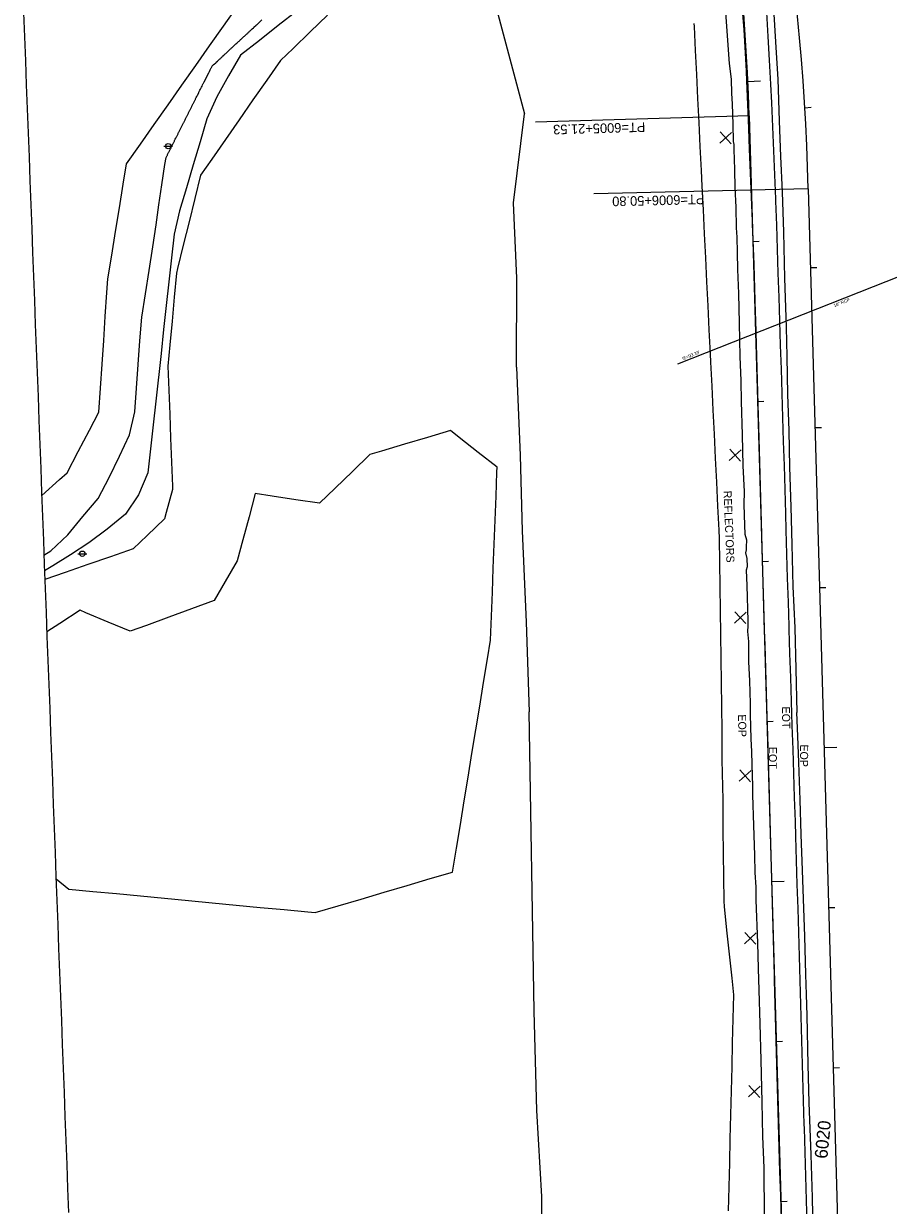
# Model space of a CAD drawing. Extents: x 2132221 to 2141942, y 535736 to 547298.
# Drawn here: x 2136695 to 2137235, y 540505 to 541244 of the extents above; entities that cross this region are included whole.
import ezdxf

# ---------------------------------------------------------------- set-up
doc = ezdxf.new("R2010")
doc.units = 0
for name, color, linetype in [('RD_EX_DR_Inlet_txCode', 7, 'Continuous'), ('RD_EX_DR_Pipe', 7, 'Continuous'), ('RD_EX_DR_Pipe_txCode', 7, 'Continuous'), ('RD_EX_Driveway', 7, 'Continuous'), ('RD_EX_Fence_Other', 7, 'Continuous'), ('RD_EX_Misc', 7, 'Continuous'), ('RD_EX_Misc_txCode', 7, 'Continuous'), ('RD_EX_Road', 7, 'Continuous'), ('RD_EX_Road_txCode', 7, 'Continuous'), ('RD_EX_SU_Pole', 7, 'Continuous'), ('RD_EX_VEG', 7, 'Continuous'), ('RD_HC_Cl', 7, 'Continuous'), ('RD_HC_Data', 7, 'Continuous'), ('RD_HC_Data_Tic', 7, 'Continuous'), ('RD_HC_TX_Sta50', 7, 'Continuous'), ('TOPO_E_TLIML-Line', 7, 'Continuous')]:
    doc.layers.add(name, color=color, linetype=linetype)

msp = doc.modelspace()

# ---------------------------------------------------------------- linework, layer by layer
at = {"layer": 'RD_EX_DR_Pipe'}
msp.add_line((2137103.49, 541031.08), (2137305.29, 541110.96), dxfattribs=at)
at = {"layer": 'RD_EX_Driveway'}
for points in [[(2136865.7, 541251.69), (2136853.89, 541242.43), (2136842.09, 541233.18), (2136830.29, 541223.93), (2136822.83, 541210.96), (2136815.56, 541197.84), (2136809.39, 541184.26), (2136805.09, 541169.89), (2136800.8, 541155.52), (2136796.51, 541141.15), (2136792.22, 541126.77), (2136788.94, 541112.2), (2136787.29, 541097.29), (2136785.64, 541082.38), (2136783.99, 541067.47), (2136782.33, 541052.56), (2136780.68, 541037.66), (2136777.38, 541007.84), (2136775.73, 540992.93), (2136774.08, 540978.02), (2136772.42, 540963.12), (2136766.71, 540949.33), (2136758.43, 540937.19), (2136747.1, 540927.78), (2136735.53, 540919.33), (2136724.2, 540911.75), (2136713.05, 540904.91), (2136707.93, 540901.76)], [(2136707.56, 540911.64), (2136711.88, 540914.22), (2136722.45, 540924.38), (2136731.94, 540935.72), (2136741.43, 540947.07), (2136748.29, 540960.11), (2136754.65, 540973.48), (2136761.01, 540986.85), (2136764.25, 541001.06), (2136765.31, 541015.85), (2136766.38, 541030.64), (2136767.44, 541045.44), (2136768.7, 541060.21), (2136773.23, 541089.52), (2136775.49, 541104.18), (2136777.57, 541117.87), (2136779.42, 541130.44), (2136781.27, 541143), (2136783.13, 541155.56), (2136783.88, 541160.06), (2136784.26, 541160.82), (2136784.45, 541161.2), (2136784.64, 541161.58), (2136784.83, 541161.95), (2136785.02, 541162.33), (2136785.21, 541162.71), (2136785.4, 541163.09), (2136785.59, 541163.46), (2136785.78, 541163.84), (2136785.97, 541164.22), (2136786.16, 541164.6), (2136786.35, 541164.98), (2136786.54, 541165.35), (2136786.73, 541165.73), (2136786.92, 541166.11), (2136787.11, 541166.49), (2136787.3, 541166.86), (2136787.49, 541167.24), (2136787.68, 541167.62), (2136788.63, 541169.51), (2136788.82, 541169.89), (2136789.01, 541170.27), (2136789.2, 541170.64), (2136789.39, 541171.02), (2136789.58, 541171.4), (2136789.96, 541172.15), (2136790.15, 541172.53), (2136790.34, 541172.91), (2136790.53, 541173.29), (2136790.72, 541173.67), (2136790.91, 541174.04), (2136791.1, 541174.42), (2136791.29, 541174.8), (2136791.48, 541175.18), (2136791.67, 541175.55), (2136791.86, 541175.93), (2136792.05, 541176.31), (2136792.24, 541176.69), (2136792.43, 541177.07), (2136792.62, 541177.44), (2136794.71, 541181.6), (2136794.9, 541181.98), (2136795.09, 541182.36), (2136795.28, 541182.73), (2136795.47, 541183.11), (2136795.66, 541183.49), (2136796.04, 541184.24), (2136796.23, 541184.62), (2136796.42, 541185), (2136796.61, 541185.38), (2136796.8, 541185.76), (2136796.99, 541186.13), (2136797.18, 541186.51), (2136797.37, 541186.89), (2136797.56, 541187.27), (2136797.75, 541187.65), (2136797.94, 541188.02), (2136798.13, 541188.4), (2136798.32, 541188.78), (2136798.51, 541189.16), (2136798.7, 541189.53), (2136798.89, 541189.91), (2136799.08, 541190.29), (2136799.46, 541191.05), (2136799.65, 541191.42), (2136799.84, 541191.8), (2136800.03, 541192.18), (2136800.22, 541192.56), (2136800.41, 541192.93), (2136800.6, 541193.31), (2136800.79, 541193.69), (2136800.98, 541194.07), (2136801.17, 541194.45), (2136801.36, 541194.82), (2136801.55, 541195.2), (2136801.74, 541195.58), (2136801.93, 541195.96), (2136802.12, 541196.34), (2136802.31, 541196.71), (2136802.69, 541197.47), (2136803.07, 541198.22), (2136803.45, 541198.98), (2136804.21, 541200.49), (2136804.4, 541200.87), (2136804.59, 541201.25), (2136804.78, 541201.62), (2136804.97, 541202), (2136805.35, 541202.76), (2136805.54, 541203.14), (2136805.73, 541203.51), (2136805.92, 541203.89), (2136806.3, 541204.65), (2136806.68, 541205.4), (2136806.87, 541205.78), (2136807.06, 541206.16), (2136807.25, 541206.54), (2136807.63, 541207.29), (2136810.48, 541212.96), (2136810.67, 541213.34), (2136810.86, 541213.72), (2136811.43, 541214.85), (2136811.62, 541215.23), (2136812, 541215.98), (2136812.19, 541216.36), (2136812.57, 541217.12), (2136812.89, 541217.43), (2136813.22, 541217.73), (2136813.55, 541218.04), (2136813.88, 541218.35), (2136814.88, 541219.27), (2136815.21, 541219.58), (2136815.87, 541220.19), (2136816.2, 541220.5), (2136816.53, 541220.8), (2136816.86, 541221.11), (2136817.19, 541221.42), (2136817.52, 541221.72), (2136817.85, 541222.03), (2136818.18, 541222.34), (2136818.84, 541222.95), (2136819.17, 541223.26), (2136819.84, 541223.87), (2136820.17, 541224.18), (2136820.83, 541224.79), (2136821.16, 541225.1), (2136821.49, 541225.41), (2136821.82, 541225.72), (2136822.15, 541226.02), (2136824.14, 541227.87), (2136824.47, 541228.17), (2136824.8, 541228.48), (2136825.13, 541228.79), (2136826.12, 541229.71), (2136826.45, 541230.01), (2136826.78, 541230.32), (2136827.44, 541230.94), (2136828.1, 541231.55), (2136828.43, 541231.86), (2136829.1, 541232.47), (2136829.43, 541232.78), (2136830.09, 541233.39), (2136830.42, 541233.7), (2136830.75, 541234.01), (2136831.08, 541234.31), (2136831.41, 541234.62), (2136831.74, 541234.93), (2136832.4, 541235.54), (2136832.73, 541235.85), (2136834.06, 541237.08), (2136834.39, 541237.38), (2136834.72, 541237.69), (2136835.05, 541238), (2136835.38, 541238.3), (2136835.71, 541238.61), (2136836.04, 541238.92), (2136836.37, 541239.23), (2136836.7, 541239.53), (2136837.69, 541240.45), (2136838.36, 541241.07), (2136838.69, 541241.38), (2136840.01, 541242.6), (2136840.34, 541242.91), (2136840.67, 541243.22), (2136843.65, 541245.98)]]:
    msp.add_lwpolyline(points, dxfattribs=at)
at = {"layer": 'RD_EX_Fence_Other'}
for p, q in [((2136990.99, 541249.71), (2137007.68, 541187.23)), ((2137013.82, 540626.7), (2137010.55, 540813.69))]:
    msp.add_line(p, q, dxfattribs=at)
for points in [[(2137002.61, 541029.05), (2137002.81, 541084.7), (2137000.84, 541131.72), (2137007.68, 541187.23)], [(2137002.61, 541029.05), (2137004.93, 540973.95), (2137006.19, 540926.7), (2137008.67, 540869.81), (2137010.55, 540813.69)], [(2137019.03, 540453.67), (2137018.59, 540510.97), (2137015.47, 540564.68), (2137013.82, 540626.7)]]:
    msp.add_lwpolyline(points, dxfattribs=at)
at = {"layer": 'RD_EX_Misc'}
for p, q in [((2137129.72, 541168.95), (2137137.07, 541175.74)), ((2137130, 541176.02), (2137136.78, 541168.67)), ((2137135.62, 540970.7), (2137142.96, 540977.48)), ((2137135.9, 540977.77), (2137142.68, 540970.42)), ((2137138.78, 540869.14), (2137146.12, 540875.93)), ((2137139.06, 540876.21), (2137145.84, 540868.86)), ((2137141.86, 540770.38), (2137149.21, 540777.17)), ((2137142.14, 540777.45), (2137148.92, 540770.1)), ((2137145.07, 540668.87), (2137152.42, 540675.66)), ((2137145.35, 540675.94), (2137152.13, 540668.59)), ((2137147.5, 540573.13), (2137154.85, 540579.91)), ((2137147.78, 540580.19), (2137154.57, 540572.84))]:
    msp.add_line(p, q, dxfattribs=at)
for points in [[(2137143.5, 541254.76), (2137144.59, 541239.8), (2137145.39, 541228.93), (2137146.08, 541213.95), (2137146.35, 541208.03), (2137146.94, 541193.04), (2137147.53, 541178.05), (2137148.04, 541165.25), (2137148.63, 541150.26), (2137149.22, 541135.27), (2137149.81, 541120.29), (2137149.88, 541118.47), (2137150.47, 541103.48), (2137150.88, 541093.25), (2137151.33, 541078.25), (2137151.78, 541063.26), (2137151.92, 541058.49), (2137152.37, 541043.5), (2137152.82, 541028.5), (2137153.27, 541013.51), (2137153.72, 540998.52), (2137154.14, 540984.62), (2137154.52, 540969.63), (2137154.91, 540954.63), (2137155.29, 540939.64), (2137155.68, 540924.64), (2137155.69, 540924.09), (2137156.14, 540909.1), (2137156.58, 540894.1), (2137157.03, 540879.11), (2137157.47, 540864.11), (2137157.72, 540855.57), (2137158.17, 540840.57), (2137158.61, 540825.58), (2137159.06, 540810.59), (2137159.4, 540798.99), (2137159.81, 540784), (2137160.23, 540769), (2137160.64, 540754.01), (2137161.06, 540739.01), (2137161.47, 540724.02), (2137161.88, 540709.02), (2137162.3, 540694.03), (2137162.71, 540679.04), (2137163.13, 540664.04), (2137163.54, 540649.05), (2137163.63, 540645.88), (2137164.04, 540630.89), (2137164.46, 540615.89), (2137164.87, 540600.9), (2137165.28, 540586.33), (2137165.72, 540571.34), (2137166.16, 540556.34), (2137166.6, 540541.35), (2137167.04, 540526.36), (2137167.49, 540511.36), (2137167.93, 540496.37)], [(2137158.91, 541250.7), (2137159.74, 541235.72), (2137160.57, 541220.75), (2137161.4, 541205.77), (2137162.04, 541194.11), (2137162.64, 541179.12), (2137163.25, 541164.14), (2137163.85, 541149.15), (2137164.45, 541134.16), (2137164.5, 541132.76), (2137164.99, 541117.77), (2137165.49, 541102.78), (2137165.98, 541087.78), (2137166.47, 541072.79), (2137166.96, 541057.8), (2137167.45, 541042.81), (2137167.95, 541027.82), (2137168.44, 541012.82), (2137168.45, 541012.51), (2137168.89, 540997.52), (2137169.33, 540982.53), (2137169.77, 540967.53), (2137170.21, 540952.54), (2137170.65, 540937.55), (2137170.95, 540927.16), (2137171.39, 540912.17), (2137171.83, 540897.18), (2137172.27, 540882.18), (2137172.71, 540867.19), (2137172.77, 540865.16), (2137173.26, 540850.17), (2137173.76, 540835.18), (2137174.25, 540820.18), (2137174.74, 540805.19), (2137175.23, 540790.2), (2137175.72, 540775.21), (2137176.21, 540760.22), (2137176.7, 540745.23), (2137177.01, 540735.89), (2137177.44, 540720.89), (2137177.88, 540705.9), (2137178.31, 540690.9), (2137178.74, 540675.91), (2137179.18, 540660.92), (2137179.61, 540645.92), (2137180.04, 540630.93), (2137180.48, 540615.94), (2137180.91, 540600.94), (2137181.34, 540585.95), (2137181.78, 540570.95), (2137182.21, 540555.96), (2137182.27, 540553.68), (2137182.71, 540538.69), (2137183.14, 540523.7), (2137183.57, 540508.7), (2137184.01, 540493.71)]]:
    msp.add_lwpolyline(points, dxfattribs=at)
at = {"layer": 'RD_EX_Road'}
for points in [[(2137131.05, 541279.98), (2137135.49, 541218.79), (2137136.72, 541208.89), (2137136.99, 541199.95), (2137137.4, 541193.5), (2137137.9, 541180.7), (2137137.94, 541169.94), (2137138.52, 541168.12), (2137138.47, 541164.98), (2137138.9, 541152.49), (2137139.14, 541140.98), (2137139.62, 541129.01), (2137139.94, 541116.05), (2137140.23, 541110.23), (2137140.45, 541100.68), (2137140.82, 541090.08), (2137141.32, 541075.08), (2137141.68, 541056.52), (2137142.26, 541035.68), (2137142.78, 541020.51), (2137143.08, 541007.62), (2137143.56, 540986.74), (2137144.13, 540967.41), (2137144.79, 540951.39), (2137144.67, 540943.25), (2137145.04, 540930.29), (2137145.4, 540924.71), (2137146.29, 540921.19), (2137146.18, 540916.66), (2137146.11, 540914.98), (2137145.77, 540913.05), (2137146.59, 540909.6), (2137146.71, 540904.22), (2137146.1, 540902.28), (2137146.54, 540892.65), (2137147.19, 540870.58), (2137147.08, 540867.38), (2137146.96, 540863.85), (2137147.62, 540857.68), (2137147.61, 540853.83), (2137147.66, 540845.01), (2137148.25, 540833.17), (2137148.56, 540818.92), (2137148.69, 540812.02), (2137149.12, 540796.81), (2137149.57, 540788.96), (2137149.63, 540780.84)], [(2137163.12, 541253.19), (2137164.61, 541228.85), (2137165.86, 541209.04), (2137166.78, 541182.88), (2137167.57, 541160.7), (2137168.65, 541138.57), (2137169.37, 541113.42), (2137170.07, 541084.6), (2137171.05, 541053.97), (2137171.56, 541035.65), (2137172.03, 541012.03), (2137172.73, 540989.5), (2137173.28, 540966.59), (2137173.94, 540941.76), (2137174.59, 540918.35), (2137175.38, 540892.12), (2137176.52, 540866.11), (2137177.17, 540840.34), (2137177.7, 540813.31)], [(2137190.73, 540393.18), (2137190.06, 540420.88), (2137189.12, 540451.38), (2137188.19, 540478), (2137187.49, 540510.25), (2137186.63, 540536.89), (2137185.47, 540569.64), (2137184.89, 540593.12), (2137184.18, 540624.07), (2137183.8, 540637.14), (2137183.4, 540649.68), (2137182.79, 540673.49), (2137182.15, 540690.86), (2137181.23, 540714.76), (2137180.43, 540737.11), (2137179.76, 540758.79), (2137179, 540782.15), (2137178.35, 540798.53), (2137177.7, 540813.31)], [(2137149.63, 540780.84), (2137150.01, 540767.31), (2137150.15, 540761.79), (2137150.74, 540742.72), (2137151.35, 540724.27), (2137151.53, 540713.38), (2137152.12, 540704.26), (2137152.23, 540696.16), (2137153.18, 540669.46), (2137153.6, 540653.34), (2137154.08, 540639.76), (2137154.68, 540619.12), (2137155.37, 540596.03), (2137156.02, 540570.16), (2137156.43, 540548.52), (2137157.12, 540528.89), (2137157.39, 540498.27)]]:
    msp.add_lwpolyline(points, dxfattribs=at)
at = {"layer": 'RD_EX_SU_Pole'}
for p, q in [((2136782.43, 541167.13), (2136787.93, 541167.13)), ((2136728.78, 540912.52), (2136734.28, 540912.52))]:
    msp.add_line(p, q, dxfattribs=at)
for centre in [(2136785.19, 541167.13), (2136731.53, 540912.52)]:
    msp.add_circle(centre, 1.65, dxfattribs=at)
at = {"layer": 'RD_EX_VEG'}
for points in [[(2136706.17, 540948.79), (2136717.32, 540958.82), (2136721.99, 540963.02), (2136728.96, 540976.3), (2136735.93, 540989.59), (2136741.86, 541000.9), (2136742.87, 541015.86), (2136743.87, 541030.83), (2136744.88, 541045.8), (2136745.89, 541060.76), (2136746.9, 541075.73), (2136747.47, 541084.14), (2136749.87, 541098.94), (2136752.27, 541113.75), (2136754.67, 541128.56), (2136757.08, 541143.36), (2136759.15, 541156.15), (2136767.79, 541168.41), (2136776.43, 541180.67), (2136785.07, 541192.94), (2136793.71, 541205.2), (2136802.35, 541217.46), (2136811, 541229.72), (2136819.64, 541241.98), (2136828.28, 541254.24)], [(2136884.69, 541249.01), (2136873.91, 541238.58), (2136863.14, 541228.14), (2136855.29, 541220.55), (2136846.7, 541208.25), (2136838.11, 541195.96), (2136829.51, 541183.66), (2136820.92, 541171.37), (2136812.32, 541159.08), (2136805.28, 541149), (2136801.72, 541134.43), (2136798.16, 541119.85), (2136794.61, 541105.28), (2136791.05, 541090.71), (2136790.32, 541087.74), (2136788.94, 541072.8), (2136787.55, 541057.87), (2136786.17, 541042.93), (2136784.93, 541029.62), (2136785.51, 541014.63), (2136786.09, 540999.64), (2136786.67, 540984.65), (2136787.25, 540969.66), (2136787.83, 540954.67), (2136787.9, 540952.68), (2136783.9, 540938.22), (2136782.79, 540934.22), (2136771.97, 540923.84), (2136763.3, 540915.52), (2136749.12, 540910.62), (2136734.94, 540905.73), (2136720.75, 540900.84), (2136708.13, 540896.49)], [(2137113.53, 541243.73), (2137113.62, 541241.89), (2137114.35, 541226.91), (2137115.09, 541211.93), (2137115.82, 541196.94), (2137116.55, 541181.96), (2137117.28, 541166.98), (2137118.01, 541152), (2137118.49, 541142.22), (2137119.22, 541127.24), (2137119.95, 541112.26), (2137120.69, 541097.28), (2137121.42, 541082.3), (2137122.15, 541067.31), (2137122.88, 541052.33), (2137123.61, 541037.35), (2137123.87, 541032.15), (2137124.6, 541017.16), (2137125.33, 541002.18), (2137126.06, 540987.2), (2137126.8, 540972.22), (2137127.53, 540957.23), (2137128.26, 540942.25), (2137128.99, 540927.27), (2137129.24, 540922.07), (2137129.44, 540907.07), (2137129.64, 540892.07), (2137129.84, 540877.07), (2137130.04, 540862.07), (2137130.24, 540847.07), (2137130.44, 540832.07), (2137130.64, 540817.08), (2137130.84, 540802.08), (2137131.04, 540787.08), (2137131.24, 540772.08), (2137131.26, 540770.46), (2137131.46, 540755.47), (2137131.66, 540740.47), (2137131.86, 540725.47), (2137132.06, 540710.47), (2137132.26, 540695.47), (2137132.3, 540692.14), (2137133.89, 540677.23), (2137135.48, 540662.31), (2137137.08, 540647.4), (2137138.2, 540636.85), (2137137.84, 540621.86), (2137137.48, 540606.86), (2137137.11, 540591.87), (2137136.75, 540576.87), (2137136.39, 540561.88), (2137136.02, 540546.88), (2137135.66, 540531.89), (2137135.3, 540516.89), (2137134.93, 540501.89)], [(2136715.13, 540709.32), (2136723.11, 540703.02), (2136738.04, 540701.59), (2136752.97, 540700.16), (2136767.9, 540698.73), (2136782.84, 540697.3), (2136797.77, 540695.87), (2136812.7, 540694.44), (2136827.63, 540693.01), (2136842.56, 540691.58), (2136857.49, 540690.15), (2136872.43, 540688.72), (2136876.89, 540688.29), (2136891.27, 540692.54), (2136905.66, 540696.79), (2136920.05, 540701.04), (2136934.43, 540705.29), (2136948.82, 540709.54), (2136962.78, 540713.66), (2136965.2, 540728.46), (2136967.62, 540743.27), (2136970.05, 540758.07), (2136972.47, 540772.87), (2136974.9, 540787.67), (2136977.32, 540802.48), (2136979.74, 540817.28), (2136982.17, 540832.08), (2136984.59, 540846.89), (2136986.5, 540858.51), (2136987.06, 540873.5), (2136987.63, 540888.49), (2136988.2, 540903.48), (2136988.77, 540918.47), (2136989.33, 540933.46), (2136989.9, 540948.45), (2136990.47, 540963.43), (2136990.59, 540966.53), (2136978.79, 540975.8), (2136966.99, 540985.06), (2136961.48, 540989.38), (2136947.1, 540985.12), (2136932.72, 540980.86), (2136918.34, 540976.59), (2136911, 540974.42), (2136900.24, 540963.97), (2136889.48, 540953.52), (2136879.69, 540944.02), (2136864.85, 540946.26), (2136850.02, 540948.51), (2136839.49, 540950.1), (2136835.63, 540935.61), (2136831.76, 540921.11), (2136828.27, 540908.01), (2136820.7, 540895.06), (2136813.78, 540883.23), (2136799.7, 540878.07), (2136785.61, 540872.91), (2136771.53, 540867.75), (2136761.43, 540864.06), (2136747.59, 540869.84), (2136733.75, 540875.63), (2136730.11, 540877.15), (2136717.55, 540868.96), (2136709.36, 540863.62)]]:
    msp.add_lwpolyline(points, dxfattribs=at)
at = {"layer": 'RD_HC_Cl'}
for p, q in [((2137147.96, 541186), (2137192.84, 539654.93)), ((2137184.88, 541140.41), (2137225.94, 539691.22))]:
    msp.add_line(p, q, dxfattribs=at)
for centre, radius, start, end in [((2135716.74, 541144.04), 1431.84, 1.67918, 36.06251), ((2135784.3, 541107.9), 1400.95, 1.32972, 36.48455)]:
    msp.add_arc(centre, radius, start, end, dxfattribs=at)
at = {"layer": 'RD_HC_Data'}
for p, q in [((2137147.96, 541186), (2137014.56, 541182.09)), ((2137147.96, 541186), (2137014.56, 541182.09)), ((2137184.88, 541140.41), (2137050.9, 541137.3))]:
    msp.add_line(p, q, dxfattribs=at)
at = {"layer": 'RD_HC_Data_Tic'}
for p, q in [((2137147.17, 541207.51), (2137155.16, 541207.87)), ((2137147.17, 541207.51), (2137155.16, 541207.87)), ((2137182.78, 541191.16), (2137186.77, 541191.4)), ((2137150.26, 541107.56), (2137154.26, 541107.68)), ((2137150.26, 541107.56), (2137154.26, 541107.68)), ((2137186.27, 541091.23), (2137190.27, 541091.34)), ((2137153.19, 541007.6), (2137157.19, 541007.72)), ((2137153.19, 541007.6), (2137157.19, 541007.72)), ((2137189.1, 540991.27), (2137193.1, 540991.38)), ((2137156.12, 540907.65), (2137160.12, 540907.76)), ((2137156.12, 540907.65), (2137160.12, 540907.76)), ((2137191.94, 540891.31), (2137195.93, 540891.42)), ((2137159.05, 540807.69), (2137163.05, 540807.81)), ((2137159.05, 540807.69), (2137163.05, 540807.81)), ((2137194.77, 540791.35), (2137202.77, 540791.58)), ((2137161.98, 540707.73), (2137169.97, 540707.97)), ((2137161.98, 540707.73), (2137169.97, 540707.97)), ((2137197.6, 540691.39), (2137201.6, 540691.5)), ((2137164.91, 540607.77), (2137168.91, 540607.89)), ((2137164.91, 540607.77), (2137168.91, 540607.89)), ((2137200.43, 540591.43), (2137204.43, 540591.54)), ((2137167.84, 540507.82), (2137171.84, 540507.93)), ((2137167.84, 540507.82), (2137171.84, 540507.93))]:
    msp.add_line(p, q, dxfattribs=at)
at = {"layer": 'TOPO_E_TLIML-Line'}
msp.add_lwpolyline([(2136694.88, 541250.47), (2136695.44, 541235.48), (2136696, 541220.49), (2136696.56, 541205.51), (2136697.13, 541190.52), (2136697.69, 541175.53), (2136698.25, 541160.54), (2136698.81, 541145.55), (2136699.37, 541130.56), (2136699.93, 541115.57), (2136700.49, 541100.58), (2136701.05, 541085.59), (2136701.61, 541070.6), (2136702.17, 541055.61), (2136702.73, 541040.62), (2136703.29, 541025.63), (2136703.86, 541010.64), (2136704.42, 540995.65), (2136704.98, 540980.66), (2136705.54, 540965.67), (2136706.1, 540950.68), (2136706.66, 540935.69), (2136707.22, 540920.7), (2136707.78, 540905.71), (2136708.34, 540890.73), (2136708.9, 540875.74), (2136709.46, 540860.75), (2136710.02, 540845.76), (2136710.59, 540830.77), (2136711.15, 540815.78), (2136711.71, 540800.79), (2136712.27, 540785.8), (2136712.83, 540770.81), (2136713.39, 540755.82), (2136713.95, 540740.83), (2136714.51, 540725.84), (2136715.07, 540710.85), (2136715.63, 540695.86), (2136716.19, 540680.87), (2136716.75, 540665.88), (2136717.32, 540650.89), (2136717.88, 540635.9), (2136718.44, 540620.91), (2136719, 540605.92), (2136719.56, 540590.94), (2136720.12, 540575.95), (2136720.68, 540560.96), (2136721.24, 540545.97), (2136721.8, 540530.98), (2136722.36, 540515.99), (2136722.92, 540501)], dxfattribs=at)

# ---------------------------------------------------------------- texts
at = {"layer": 'RD_EX_DR_Inlet_txCode'}
msp.add_text("IE=93.33'", height=2, rotation=21.59513, dxfattribs=at).set_placement((2137106.61, 541033.39))
at = {"layer": 'RD_EX_DR_Pipe_txCode'}
msp.add_text('18" RCP', height=2, rotation=21.59513, dxfattribs=at).set_placement((2137201.21, 541066.53))
at = {"layer": 'RD_EX_Misc_txCode'}
for s, rotation, p in [('REFLECTORS', 272.4106, (2137131.98, 540951.77)), ('EOT', 271.05301, (2137168.46, 540816.98)), ('EOT', 269.67857, (2137160.33, 540791.88))]:
    msp.add_text(s, height=5, rotation=rotation, dxfattribs=at).set_placement(p)
at = {"layer": 'RD_EX_Road_txCode'}
for rotation, p in [(271.24074, (2137141.04, 540812.11)), (269.57466, (2137179.87, 540793.43))]:
    msp.add_text('EOP', height=5, rotation=rotation, dxfattribs=at).set_placement(p)
at = {"layer": 'RD_HC_Data'}
for s, rotation, p in [('PT=6005+21.53', 181.67918, (2137083.04, 541182.09)), ('PT=6005+21.53', 181.67918, (2137083.04, 541182.09)), ('PT=6006+50.80', 181.32972, (2137119.94, 541136.9))]:
    msp.add_text(s, height=6, rotation=rotation, dxfattribs=at).set_placement(p)
at = {"layer": 'RD_HC_TX_Sta50'}
msp.add_text('6020', height=8, rotation=84.15685, dxfattribs=at).set_placement((2137196.76, 540534.31))

doc.saveas('drawing.dxf')
